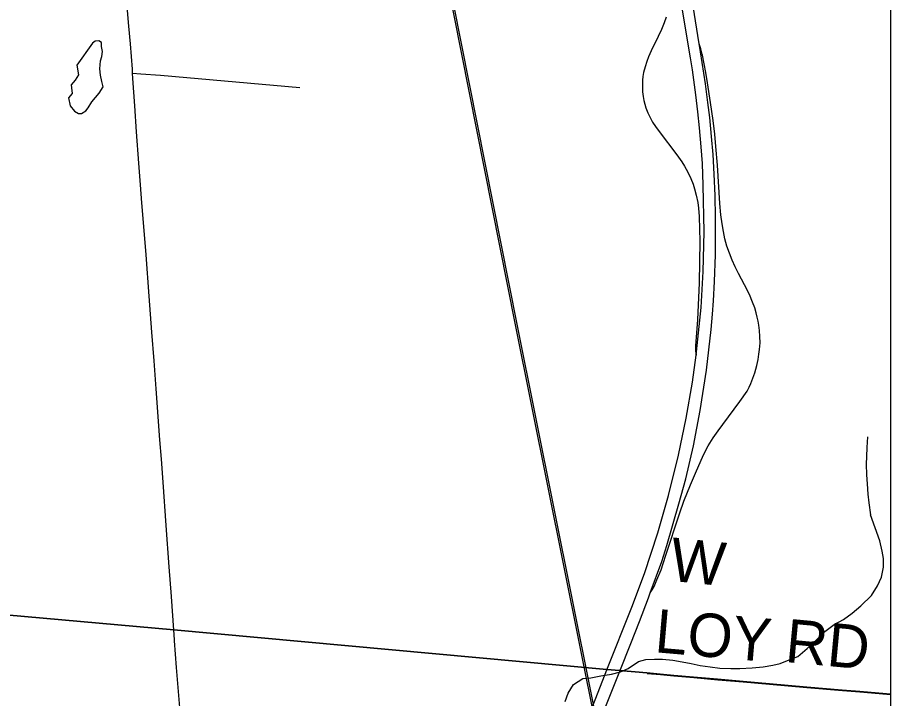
# Model space of a CAD drawing. Extents: x -87 to 2145, y -2128 to 440.
# Drawn here: x 199.98 to 230.18, y -1186.1 to -1162.55 of the extents above; entities that cross this region are included whole.
import ezdxf

# ---------------------------------------------------------------- set-up
doc = ezdxf.new("R2010")
doc.units = 0
for name, color, linetype in [('GM_X_City_Street', 7, 'Continuous'), ('GM_X_County_Road', 7, 'Continuous'), ('GM_X_County_Road_Text', 7, 'Continuous'), ('GM_X_Interchange_Ramps', 7, 'Continuous'), ('GM_X_Interstate_Route', 7, 'Continuous'), ('GM_X_Minor_Lake', 7, 'Continuous'), ('GM_X_Minor_River', 7, 'Continuous'), ('GM_X_Rail_Line', 7, 'Continuous'), ('GM_X_Township_Text', 7, 'Continuous'), ('SC_Scratch1', 7, 'Continuous')]:
    doc.layers.add(name, color=color, linetype=linetype)

msp = doc.modelspace()

# ---------------------------------------------------------------- linework, layer by layer
at = {"layer": 'GM_X_City_Street'}
msp.add_lwpolyline([(203.965, -1164.472), (204.248, -1164.492), (204.936, -1164.541), (209.753, -1164.971)], dxfattribs=at)
at = {"layer": 'GM_X_County_Road'}
for points in [[(203.965, -1164.472), (203.957, -1164.333), (203.887, -1163.466), (203.835, -1162.845), (203.793, -1162.306), (203.753, -1161.75), (203.695, -1161.047), (203.659, -1160.623), (203.638, -1160.361), (203.622, -1160.165), (203.588, -1159.871), (203.548, -1159.611), (203.501, -1159.385), (203.46, -1159.222)], [(204.536, -1172.181), (204.429, -1170.759), (204.355, -1169.777), (204.29, -1168.96), (204.239, -1168.34), (204.185, -1167.587), (204.105, -1166.508), (204.044, -1165.608), (203.975, -1164.66), (203.965, -1164.472)], [(205.394, -1183.76), (205.392, -1183.735), (205.31, -1182.571), (205.235, -1181.54), (205.126, -1180.117), (205.019, -1178.612), (204.96, -1177.827), (204.906, -1177.157), (204.778, -1175.392), (204.714, -1174.426), (204.636, -1173.429), (204.536, -1172.181)], [(205.419, -1184.1), (205.401, -1183.863), (205.394, -1183.76)], [(209.858, -1204.32), (209.398, -1203.309), (208.121, -1200.466), (207.66, -1199.45), (207.1, -1198.192), (206.936, -1197.799), (206.826, -1197.509), (206.752, -1197.275), (206.69, -1197.022), (206.533, -1196.218), (206.341, -1195.136), (206.274, -1194.716), (206.222, -1194.31), (206.162, -1193.706), (206.017, -1191.991), (205.944, -1191.108), (205.871, -1190.143), (205.776, -1188.884), (205.608, -1186.544), (205.489, -1185.024), (205.419, -1184.1)], [(221.764, -1185.228), (222.221, -1185.268), (222.693, -1185.311), (223.375, -1185.374), (224.204, -1185.446), (225.086, -1185.525), (226.001, -1185.606), (227.293, -1185.716), (228.518, -1185.821), (229.124, -1185.872), (230.183, -1185.964)]]:
    msp.add_lwpolyline(points, dxfattribs=at)
at = {"layer": 'GM_X_Interchange_Ramps'}
for points in [[(222.418, -1162.536), (222.351, -1162.739), (222.259, -1162.967), (222.148, -1163.205), (221.902, -1163.705), (221.807, -1163.915), (221.748, -1164.068), (221.69, -1164.256), (221.642, -1164.447), (221.614, -1164.592), (221.601, -1164.722), (221.599, -1164.919), (221.608, -1165.116), (221.624, -1165.279), (221.649, -1165.425), (221.681, -1165.552), (221.721, -1165.677), (221.788, -1165.844), (221.866, -1166.007), (221.954, -1166.165), (222.051, -1166.317), (222.176, -1166.489), (222.79, -1167.3), (222.959, -1167.543), (223.055, -1167.695), (223.169, -1167.895), (223.274, -1168.118), (223.352, -1168.316), (223.403, -1168.472), (223.462, -1168.694), (223.512, -1168.952), (223.537, -1169.147), (223.56, -1169.425), (223.579, -1169.868), (223.587, -1170.278), (223.561, -1171.722), (223.507, -1173.004), (223.438, -1173.904), (223.435, -1173.976), (223.435, -1174.072), (223.455, -1174.225)], [(221.874, -1182.448), (221.94, -1182.335), (222.003, -1182.227), (222.105, -1181.996), (222.245, -1181.646), (222.404, -1181.181), (222.893, -1179.672), (223.038, -1179.274), (223.264, -1178.704), (223.433, -1178.302), (223.709, -1177.669), (223.875, -1177.36), (224.046, -1177.081), (224.218, -1176.84), (224.384, -1176.621), (224.971, -1175.83), (225.22, -1175.469), (225.294, -1175.331), (225.348, -1175.204), (225.487, -1174.841), (225.563, -1174.587), (225.607, -1174.372), (225.633, -1174.194), (225.651, -1174.024), (225.669, -1173.798), (225.663, -1173.578), (225.651, -1173.37), (225.627, -1173.192), (225.604, -1173.05), (225.574, -1172.913), (225.538, -1172.759), (225.485, -1172.592), (225.414, -1172.39), (225.301, -1172.129), (225.129, -1171.796), (224.925, -1171.4), (224.806, -1171.171), (224.703, -1170.941), (224.608, -1170.703), (224.523, -1170.456), (224.456, -1170.202), (224.401, -1169.946), (224.357, -1169.687), (224.318, -1169.378), (224.284, -1168.986), (224.195, -1167.66), (224.144, -1167.006), (224.102, -1166.581), (224.046, -1166.109), (223.961, -1165.492), (223.855, -1164.811), (223.792, -1164.448), (223.68, -1163.856), (223.671, -1163.816), (223.621, -1163.634), (223.564, -1163.462)]]:
    msp.add_lwpolyline(points, dxfattribs=at)
at = {"layer": 'GM_X_Interstate_Route'}
for points in [[(223.455, -1174.225), (223.499, -1173.888), (223.628, -1172.581), (223.706, -1171.336), (223.74, -1169.958), (223.707, -1168.35), (223.674, -1167.595), (223.636, -1167.022), (223.58, -1166.368), (223.523, -1165.813), (223.451, -1165.226), (223.328, -1164.365), (223.264, -1163.943), (222.666, -1160.351), (222.421, -1158.844), (222.41, -1158.776), (222.302, -1158.15), (222.197, -1157.493)], [(221.197, -1184.191), (221.499, -1183.431), (221.812, -1182.62), (221.874, -1182.448), (222.268, -1181.355), (222.445, -1180.81), (222.866, -1179.362), (223.097, -1178.507), (223.366, -1177.358), (223.599, -1176.134), (223.813, -1174.741), (223.9, -1174.042), (223.974, -1173.341), (224.023, -1172.802), (224.056, -1172.344), (224.091, -1171.673), (224.124, -1170.756), (224.134, -1170.166), (224.133, -1169.461), (224.116, -1168.707), (224.085, -1167.97), (224.044, -1167.283), (223.994, -1166.662), (223.93, -1166.009), (223.868, -1165.488), (223.779, -1164.839), (223.609, -1163.737), (223.564, -1163.462), (222.823, -1158.811)], [(219.172, -1188.121), (219.989, -1186.08), (220.375, -1185.106), (221.233, -1182.939), (221.668, -1181.77), (222.132, -1180.367), (222.508, -1179.074), (222.848, -1177.688), (223.119, -1176.403), (223.332, -1175.157), (223.455, -1174.225)], [(212.71, -1205.601), (212.886, -1205.158), (213.867, -1202.707), (215.486, -1198.601), (216.817, -1195.265), (217.795, -1192.777), (219.005, -1189.694), (219.964, -1187.286), (220.816, -1185.147), (221.197, -1184.191)]]:
    msp.add_lwpolyline(points, dxfattribs=at)
at = {"layer": 'GM_X_Minor_Lake'}
for points in [[(202.573, -1163.434), (202.038, -1164.196), (202.093, -1164.527), (201.979, -1164.715), (201.836, -1164.873), (201.854, -1164.983), (201.871, -1165.174), (201.748, -1165.322), (201.804, -1165.603), (201.961, -1165.786), (202.09, -1165.868), (202.2, -1165.87)], [(202.2, -1165.87), (202.352, -1165.782), (202.434, -1165.673), (202.558, -1165.465), (202.804, -1165.169), (202.948, -1164.951), (202.901, -1164.76), (202.854, -1164.549), (202.828, -1164.319), (202.853, -1164.049), (202.906, -1163.9), (202.929, -1163.73), (202.892, -1163.549), (202.884, -1163.409), (202.795, -1163.358), (202.674, -1163.366), (202.573, -1163.434)]]:
    msp.add_lwpolyline(points, dxfattribs=at)
at = {"layer": 'GM_X_Minor_River'}
for points in [[(229.384, -1177.054), (229.369, -1177.414), (229.355, -1177.724), (229.341, -1177.995), (229.356, -1178.366), (229.371, -1178.677), (229.396, -1179.028), (229.432, -1179.329), (229.487, -1179.75)], [(218.928, -1186.199), (219.035, -1185.911), (219.222, -1185.615), (219.537, -1185.411), (219.818, -1185.377), (220.16, -1185.315), (220.532, -1185.253), (220.845, -1185.179), (221.108, -1185.055), (221.464, -1184.812), (221.716, -1184.748), (222.017, -1184.734), (222.297, -1184.74), (222.647, -1184.768), (222.977, -1184.825), (223.286, -1184.881), (223.604, -1184.958), (223.944, -1185.006), (224.284, -1185.043), (224.654, -1185.061), (224.975, -1185.058), (225.396, -1185.037), (225.777, -1185.005), (226.109, -1184.942), (226.361, -1184.887), (226.624, -1184.783), (226.977, -1184.65), (227.294, -1184.367), (227.55, -1184.132), (227.868, -1183.809), (228.235, -1183.536), (228.56, -1183.363), (228.855, -1183.149), (229.152, -1182.895), (229.521, -1182.533), (229.729, -1182.197), (229.866, -1181.899), (229.944, -1181.561), (229.941, -1181.26), (229.897, -1180.999), (229.815, -1180.647), (229.487, -1179.75)]]:
    msp.add_lwpolyline(points, dxfattribs=at)
at = {"layer": 'GM_X_Rail_Line'}
for points in [[(221.669, -1195.387), (217.209, -1173.171), (211.624, -1145.03), (211.053, -1142.113), (210.114, -1137.448)], [(225.434, -1214.375), (225.312, -1213.385), (224.249, -1207.809), (221.734, -1195.374), (217.273, -1173.158), (211.484, -1143.974), (211.271, -1143.225)]]:
    msp.add_lwpolyline(points, dxfattribs=at)
at = {"layer": 'GM_X_Township_Text'}
for points in [[(230.183, -1185.951), (229.117, -1185.858), (228.512, -1185.807), (227.287, -1185.702), (225.995, -1185.592), (225.08, -1185.511), (224.197, -1185.432), (223.369, -1185.36), (222.687, -1185.297), (222.215, -1185.253), (221.758, -1185.214), (220.81, -1185.133), (220.368, -1185.092), (205.386, -1183.721), (195.693, -1182.854), (195.437, -1185.773), (195.174, -1186.997)], [(195.693, -1182.854), (205.386, -1183.721), (220.368, -1185.092), (220.81, -1185.133), (221.758, -1185.214), (222.215, -1185.253), (222.687, -1185.297), (223.369, -1185.36), (224.197, -1185.432), (225.08, -1185.511), (225.995, -1185.592), (227.287, -1185.702), (228.512, -1185.807), (229.117, -1185.858), (230.183, -1185.951)]]:
    msp.add_lwpolyline(points, dxfattribs=at)
at = {"layer": 'SC_Scratch1'}
msp.add_lwpolyline([(-21.617, -825.188), (230.183, -825.188), (230.183, -1245.188), (-21.617, -1245.188)], close=True, dxfattribs=at)

# ---------------------------------------------------------------- texts
at = {"layer": 'GM_X_County_Road_Text'}
for s, rotation, p in [('W', 354.2179, (222.506, -1182.02)), ('LOY', 355.0029, (221.994, -1184.493)), ('RD', 354.6289, (226.503, -1184.831))]:
    msp.add_text(s, height=1.5, rotation=rotation, dxfattribs=at).set_placement(p)

doc.saveas('drawing.dxf')
